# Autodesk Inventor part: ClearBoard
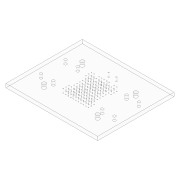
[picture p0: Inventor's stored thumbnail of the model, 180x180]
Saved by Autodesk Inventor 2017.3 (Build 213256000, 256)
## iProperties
Part Number: ClearBoard
Material: PET プラスチック
Document SubType Name: Modeling
Designer: kyushu-hep
Density: 1.541 g/cm^3
Appearance: ポリカーボネート - クリア
Author: kyushu-hep
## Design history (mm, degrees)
sketch "スケッチ1"
  geometry: L1 (60, -50)-(-60, -50); L2 (-60, -50)-(-60, 50); L3 (-60, 50)-(60, 50); L4 (60, 50)-(60, -50); L5 (60, -50)-(-60, 50); L6 (-60, -50)-(60, 50); 1 further point
  constraints: 12 end point, 2 midpoint, 2 parallel, 1 horizontal, 1 perpendicular
  dimensions: "d0" = 120 distance of L2.end L3.end; "d1" = 100 distance of L1.end L2.end
extrude "押し出し1" new body sketch "スケッチ1" distance "d2" = 5; taper "d3" = 0 deg
sketch "スケッチ2"
  geometry: L1 (-100, 50)-(-100, -50); L2 (-100, -50)-(100, -50); C1 r 0.75 at (-5.05, 29.5); C2 r 0.75 at (5.05, 29.5); 2 further points
  constraints: 4 end point, 2 centre point
  dimensions: "d4" = 1.5 diameter of C1; "d5" = 1.5 diameter of C2; "d6" = 10.1 distance of C2.centre C1.centre; "d7" = 29.5 vertical distance of point (0, 0) C2.centre; "d8" = 5.05 horizontal distance of C1.centre point (0, 0)
extrude "押し出し2" cut sketch "スケッチ2" distance "d9" = 5; taper "d10" = 0 deg
sketch "スケッチ3"
  geometry: C1 r 2.5 at (-35, 25); C2 r 2.5 at (35, 25); C3 r 2.5 at (-35, -25); C4 r 2.5 at (35, -25); 1 further point
  constraints: 4 centre point
  dimensions: "d11" = 5 diameter of C1; "d14" = 25 vertical distance of C1.centre point (0, 0); "d15" = 35 horizontal distance of C1.centre point (0, 0); "d18" = 5 diameter of C2; "d19" = 35 horizontal distance of point (0, 0) C2.centre; "d20" = 25 vertical distance of C2.centre point (0, 0); "d21" = 5 diameter of C3; "d22" = 25 vertical distance of point (0, 0) C3.centre; "d23" = 35 horizontal distance of point (0, 0) C3.centre; "d24" = 5 diameter of C4; "d25" = 25 vertical distance of point (0, 0) C4.centre; "d26" = 35 horizontal distance of point (0, 0) C4.centre
extrude "押し出し3" cut sketch "スケッチ3" distance "d27" = 5; taper "d28" = 0 deg
feature "ねじ1" dims "d29" = 10, "d30" = 0
feature "ねじ2" dims "d31" = 10, "d32" = 0
feature "ねじ3" dims "d33" = 10, "d34" = 0
feature "ねじ4" dims "d35" = 10, "d36" = 0
sketch "スケッチ5"
  geometry: L1 (17.5, -19.5)-(-17.5, -19.5); L2 (-17.5, -19.5)-(-17.5, 19.5); L3 (-17.5, 19.5)-(17.5, 19.5); L4 (17.5, 19.5)-(17.5, -19.5); L5 (17.5, -19.5)-(-17.5, 19.5); L6 (-17.5, -19.5)-(17.5, 19.5); C1 r 0.5 at (-16.5, 18.5); C2 r 0.5 at (-13.2, 18.5); C3 r 0.5 at (-9.9, 18.5); C4 r 0.5 at (-6.6, 18.5); C5 r 0.5 at (-3.3, 18.5); C6 r 0.5 at (0, 18.5); C7 r 0.5 at (3.3, 18.5); C8 r 0.5 at (6.6, 18.5); C9 r 0.5 at (9.9, 18.5); C10 r 0.5 at (13.2, 18.5); C11 r 0.5 at (-16.5, 14.8); C12 r 0.5 at (-13.2, 14.8); C13 r 0.5 at (-9.9, 14.8); C14 r 0.5 at (-6.6, 14.8); C15 r 0.5 at (-3.3, 14.8); C16 r 0.5 at (0, 14.8); C17 r 0.5 at (3.3, 14.8); C18 r 0.5 at (6.6, 14.8); C19 r 0.5 at (9.9, 14.8); C20 r 0.5 at (13.2, 14.8); C21 r 0.5 at (16.5, 18.5); C22 r 0.5 at (16.5, 14.8); C23 r 0.5 at (-16.5, 11.1); C24 r 0.5 at (-13.2, 11.1); C25 r 0.5 at (-9.9, 11.1); C26 r 0.5 at (-6.6, 11.1); C27 r 0.5 at (-3.3, 11.1); C28 r 0.5 at (0, 11.1); C29 r 0.5 at (3.3, 11.1); C30 r 0.5 at (6.6, 11.1); C31 r 0.5 at (9.9, 11.1); C32 r 0.5 at (13.2, 11.1); C33 r 0.5 at (16.5, 11.1); C34 r 0.5 at (-16.5, 7.4); C35 r 0.5 at (-13.2, 7.4); C36 r 0.5 at (-9.9, 7.4); C37 r 0.5 at (-6.6, 7.4); C38 r 0.5 at (-3.3, 7.4); C39 r 0.5 at (0, 7.4); C40 r 0.5 at (3.3, 7.4); C41 r 0.5 at (6.6, 7.4); C42 r 0.5 at (9.9, 7.4); C43 r 0.5 at (13.2, 7.4); C44 r 0.5 at (16.5, 7.4); C45 r 0.5 at (-16.5, 3.7); C46 r 0.5 at (-13.2, 3.7); C47 r 0.5 at (-9.9, 3.7); C48 r 0.5 at (-6.6, 3.7); C49 r 0.5 at (-3.3, 3.7); C50 r 0.5 at (0, 3.7); C51 r 0.5 at (3.3, 3.7); C52 r 0.5 at (6.6, 3.7); C53 r 0.5 at (9.9, 3.7); C54 r 0.5 at (13.2, 3.7); C55 r 0.5 at (16.5, 3.7); C56 r 0.5 at (-16.5, 0); C57 r 0.5 at (-13.2, 0); C58 r 0.5 at (-9.9, 0); C59 r 0.5 at (-6.6, 0); C60 r 0.5 at (-3.3, 0); C61 r 0.5 at (0, 0); C62 r 0.5 at (3.3, 0); C63 r 0.5 at (6.6, 0); C64 r 0.5 at (9.9, 0)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; 1 further point
  constraints: 121 centre point, 12 end point, 2 horizontal, 2 midpoint, 2 parallel, 1 perpendicular, 1 vertical, 240 other
  dimensions: "d58" = 35 distance of L2.end L3.end; "d59" = 39 distance of L3.end L1.start; "d60" = 1 diameter of C1; "d61" = 16.5 horizontal distance of point (0, 0) C1.centre; "d62" = 18.5 vertical distance of point (0, 0) C1.centre; "d65" = 3.3 distance of C1.centre C2.centre; "d68" = 3.7 distance of C1.centre C11.centre
extrude "押し出し10" cut sketch "スケッチ5" distance "d89" = 10; taper "d90" = 0 deg
sketch "スケッチ7"
  geometry: L1 (20, 20)-(-20, 20); L2 (-20, 20)-(-20, -20); L3 (-20, -20)-(20, -20); L4 (20, -20)-(20, 20); L5 (20, 20)-(-20, -20); L6 (-20, 20)-(20, -20); C1 r 1.75 at (-48, -16); C2 r 1.75 at (-48, 16); C3 r 1.75 at (-32, -16); C4 r 1.75 at (-32, 16); C5 r 1.75 at (-16, -16); C6 r 1.75 at (-16, 16); C7 r 1.75 at (0, -16); C8 r 1.75 at (0, 16); C9 r 1.75 at (16, -16); C10 r 1.75 at (16, 16); C11 r 1.75 at (32, -16); C12 r 1.75 at (32, 16); C13 r 1.75 at (48, -16); C14 r 1.75 at (48, 16); 2 further points
  constraints: 14 centre point, 12 end point, 2 horizontal, 2 midpoint, 2 parallel, 1 perpendicular, 1 vertical, 26 other
  dimensions: "d95" = 3.5 diameter of C1; "d96" = 48 horizontal distance of point (0, 0) C1.centre; "d97" = 16 vertical distance of point (0, 0) C1.centre; "d98" = 40 distance of L3.end L2.end; "d99" = 40 distance of L2.end L1.end; "d100" = 32 distance of C1.centre C2.centre; "d101" = 16 distance of C1.centre C3.centre
extrude "押し出し11" cut sketch "スケッチ7" distance "d102" = 5; taper "d103" = 0 deg
node "ソリッド1"
